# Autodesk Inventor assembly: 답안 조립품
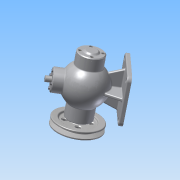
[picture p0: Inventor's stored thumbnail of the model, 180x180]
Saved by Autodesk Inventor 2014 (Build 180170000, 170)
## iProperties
Created: 2017-01
Part Number: 답안 조립품
Document SubType Name: Assembly
Designer: ksu
Author: ksu
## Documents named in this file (19)
- C:\Users\ksu\Desktop\답안 조립품.iam
- C:\Users\ksu\Desktop\본체.ipt
- C:\Users\ksu\Desktop\470118V1004\V-벨트풀리.ipt
- C:\Users\ksu\Desktop\470118V1004\너트 M8.ipt
- C:\Users\ksu\Desktop\470118V1004\뒤커버.ipt
- C:\Users\ksu\Desktop\470118V1004\멈춤링- 15 x 1.ipt
- C:\Users\ksu\Desktop\470118V1004\멈춤링- 35x1.6.ipt
- KS B 1336 - 35x1.6.ipt
- C:\Users\ksu\Desktop\470118V1004\베어링- 6202.ipt
- KS B 2023 - 6202 - 15 x 35 x 11 - 7.8.ipt
- C:\Users\ksu\Desktop\470118V1004\볼트 M4 x 12.ipt
- C:\Users\ksu\Desktop\470118V1004\볼트 M4 x 16.ipt
- C:\Users\ksu\Desktop\470118V1004\부시.ipt
- C:\Users\ksu\Desktop\470118V1004\상부커버.ipt
- C:\Users\ksu\Desktop\470118V1004\슬라이드.ipt
- C:\Users\ksu\Desktop\470118V1004\앞커버.ipt
- C:\Users\ksu\Desktop\470118V1004\오일실 15 30 7.ipt
- C:\Users\ksu\Desktop\470118V1004\키 4 x 4 x 12.ipt
- C:\Users\ksu\Desktop\470118V1004\편심축.ipt
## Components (16 placed, 5 different names)
1. V-벨트풀리:1 — Mate:17, Mate:18, Mate:19, Insert:4
2. KS B 1336 - 35x1.6:1 — Mate:4, Mate:5, Mate:10
3. KS B 2023 - 6202 - 15 x 35 x 11 - 7.8:1 — Mate:30, Mate:31, Mate:32, Mate:34
4. KS B 2023 - 6202 - 15 x 35 x 11 - 7.8:2 — Mate:8, Mate:9, Mate:10
5. KS B 1021 - 에 따름 ISO 1207 - 미터 A  M 4 x 12:1 — Mate:23, Mate:24
6. KS B 1021 - 에 따름 ISO 1207 - 미터 A  M 4 x 12:2
7. KS B 1021 - 에 따름 ISO 1207 - 미터 A  M 4 x 12:3
8. KS B 1021 - 에 따름 ISO 1207 - 미터 A  M 4 x 12:4
9. ISO 4762 M4 x 16:1 — Mate:25, Mate:26
10. ISO 4762 M4 x 16:3
11. ISO 4762 M4 x 16:4
12. ISO 4762 M4 x 16:5
13. ISO 4762 M4 x 16:2 — Mate:27, Mate:28
14. ISO 4762 M4 x 16:6
15. ISO 4762 M4 x 16:7
16. ISO 4762 M4 x 16:8
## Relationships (19: Mate 18, Insert 1)
- Mate:4: KS B 1336 - 35x1.6:1
- Mate:5: KS B 1336 - 35x1.6:1
- Mate:8: KS B 2023 - 6202 - 15 x 35 x 11 - 7.8:2
- Mate:9: KS B 2023 - 6202 - 15 x 35 x 11 - 7.8:2
- Mate:10: KS B 1336 - 35x1.6:1 ↔ KS B 2023 - 6202 - 15 x 35 x 11 - 7.8:2
- Mate:17: V-벨트풀리:1
- Mate:18: V-벨트풀리:1
- Mate:19: V-벨트풀리:1
- Insert:4: V-벨트풀리:1
- Mate:23: KS B 1021 - 에 따름 ISO 1207 - 미터 A  M 4 x 12:1
- Mate:24: KS B 1021 - 에 따름 ISO 1207 - 미터 A  M 4 x 12:1
- Mate:25: ISO 4762 M4 x 16:1
- Mate:26: ISO 4762 M4 x 16:1
- Mate:27: ISO 4762 M4 x 16:2
- Mate:28: ISO 4762 M4 x 16:2
- Mate:30: KS B 2023 - 6202 - 15 x 35 x 11 - 7.8:1
- Mate:31: KS B 2023 - 6202 - 15 x 35 x 11 - 7.8:1
- Mate:32: KS B 2023 - 6202 - 15 x 35 x 11 - 7.8:1
- Mate:34: KS B 2023 - 6202 - 15 x 35 x 11 - 7.8:1
